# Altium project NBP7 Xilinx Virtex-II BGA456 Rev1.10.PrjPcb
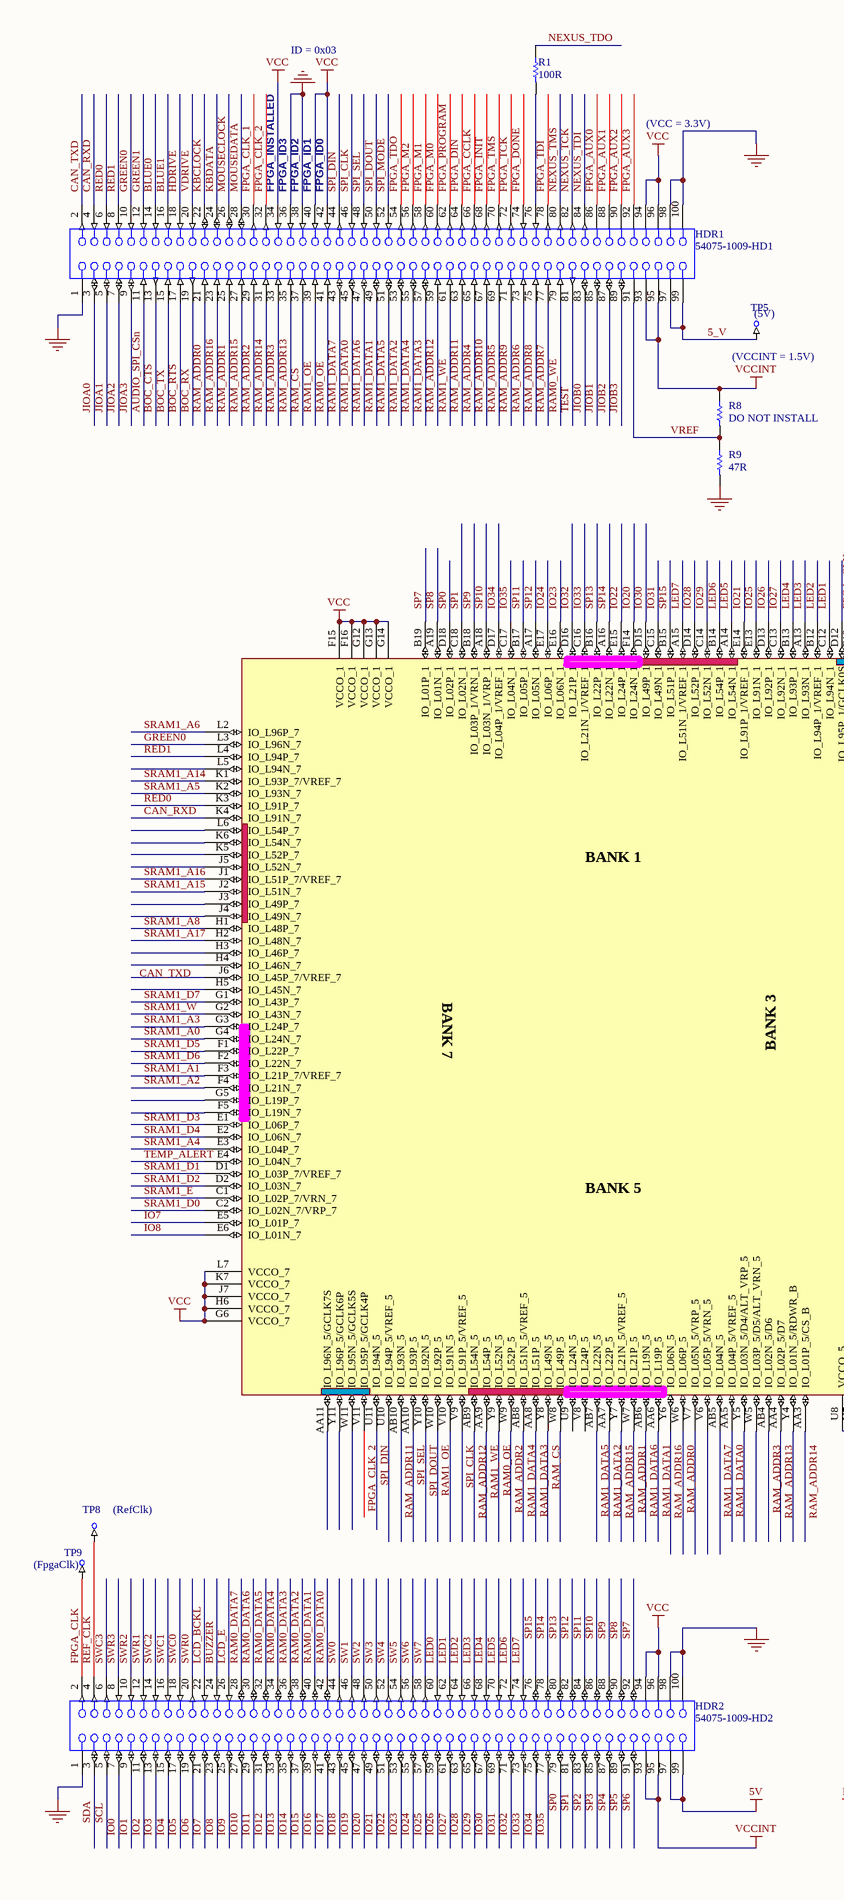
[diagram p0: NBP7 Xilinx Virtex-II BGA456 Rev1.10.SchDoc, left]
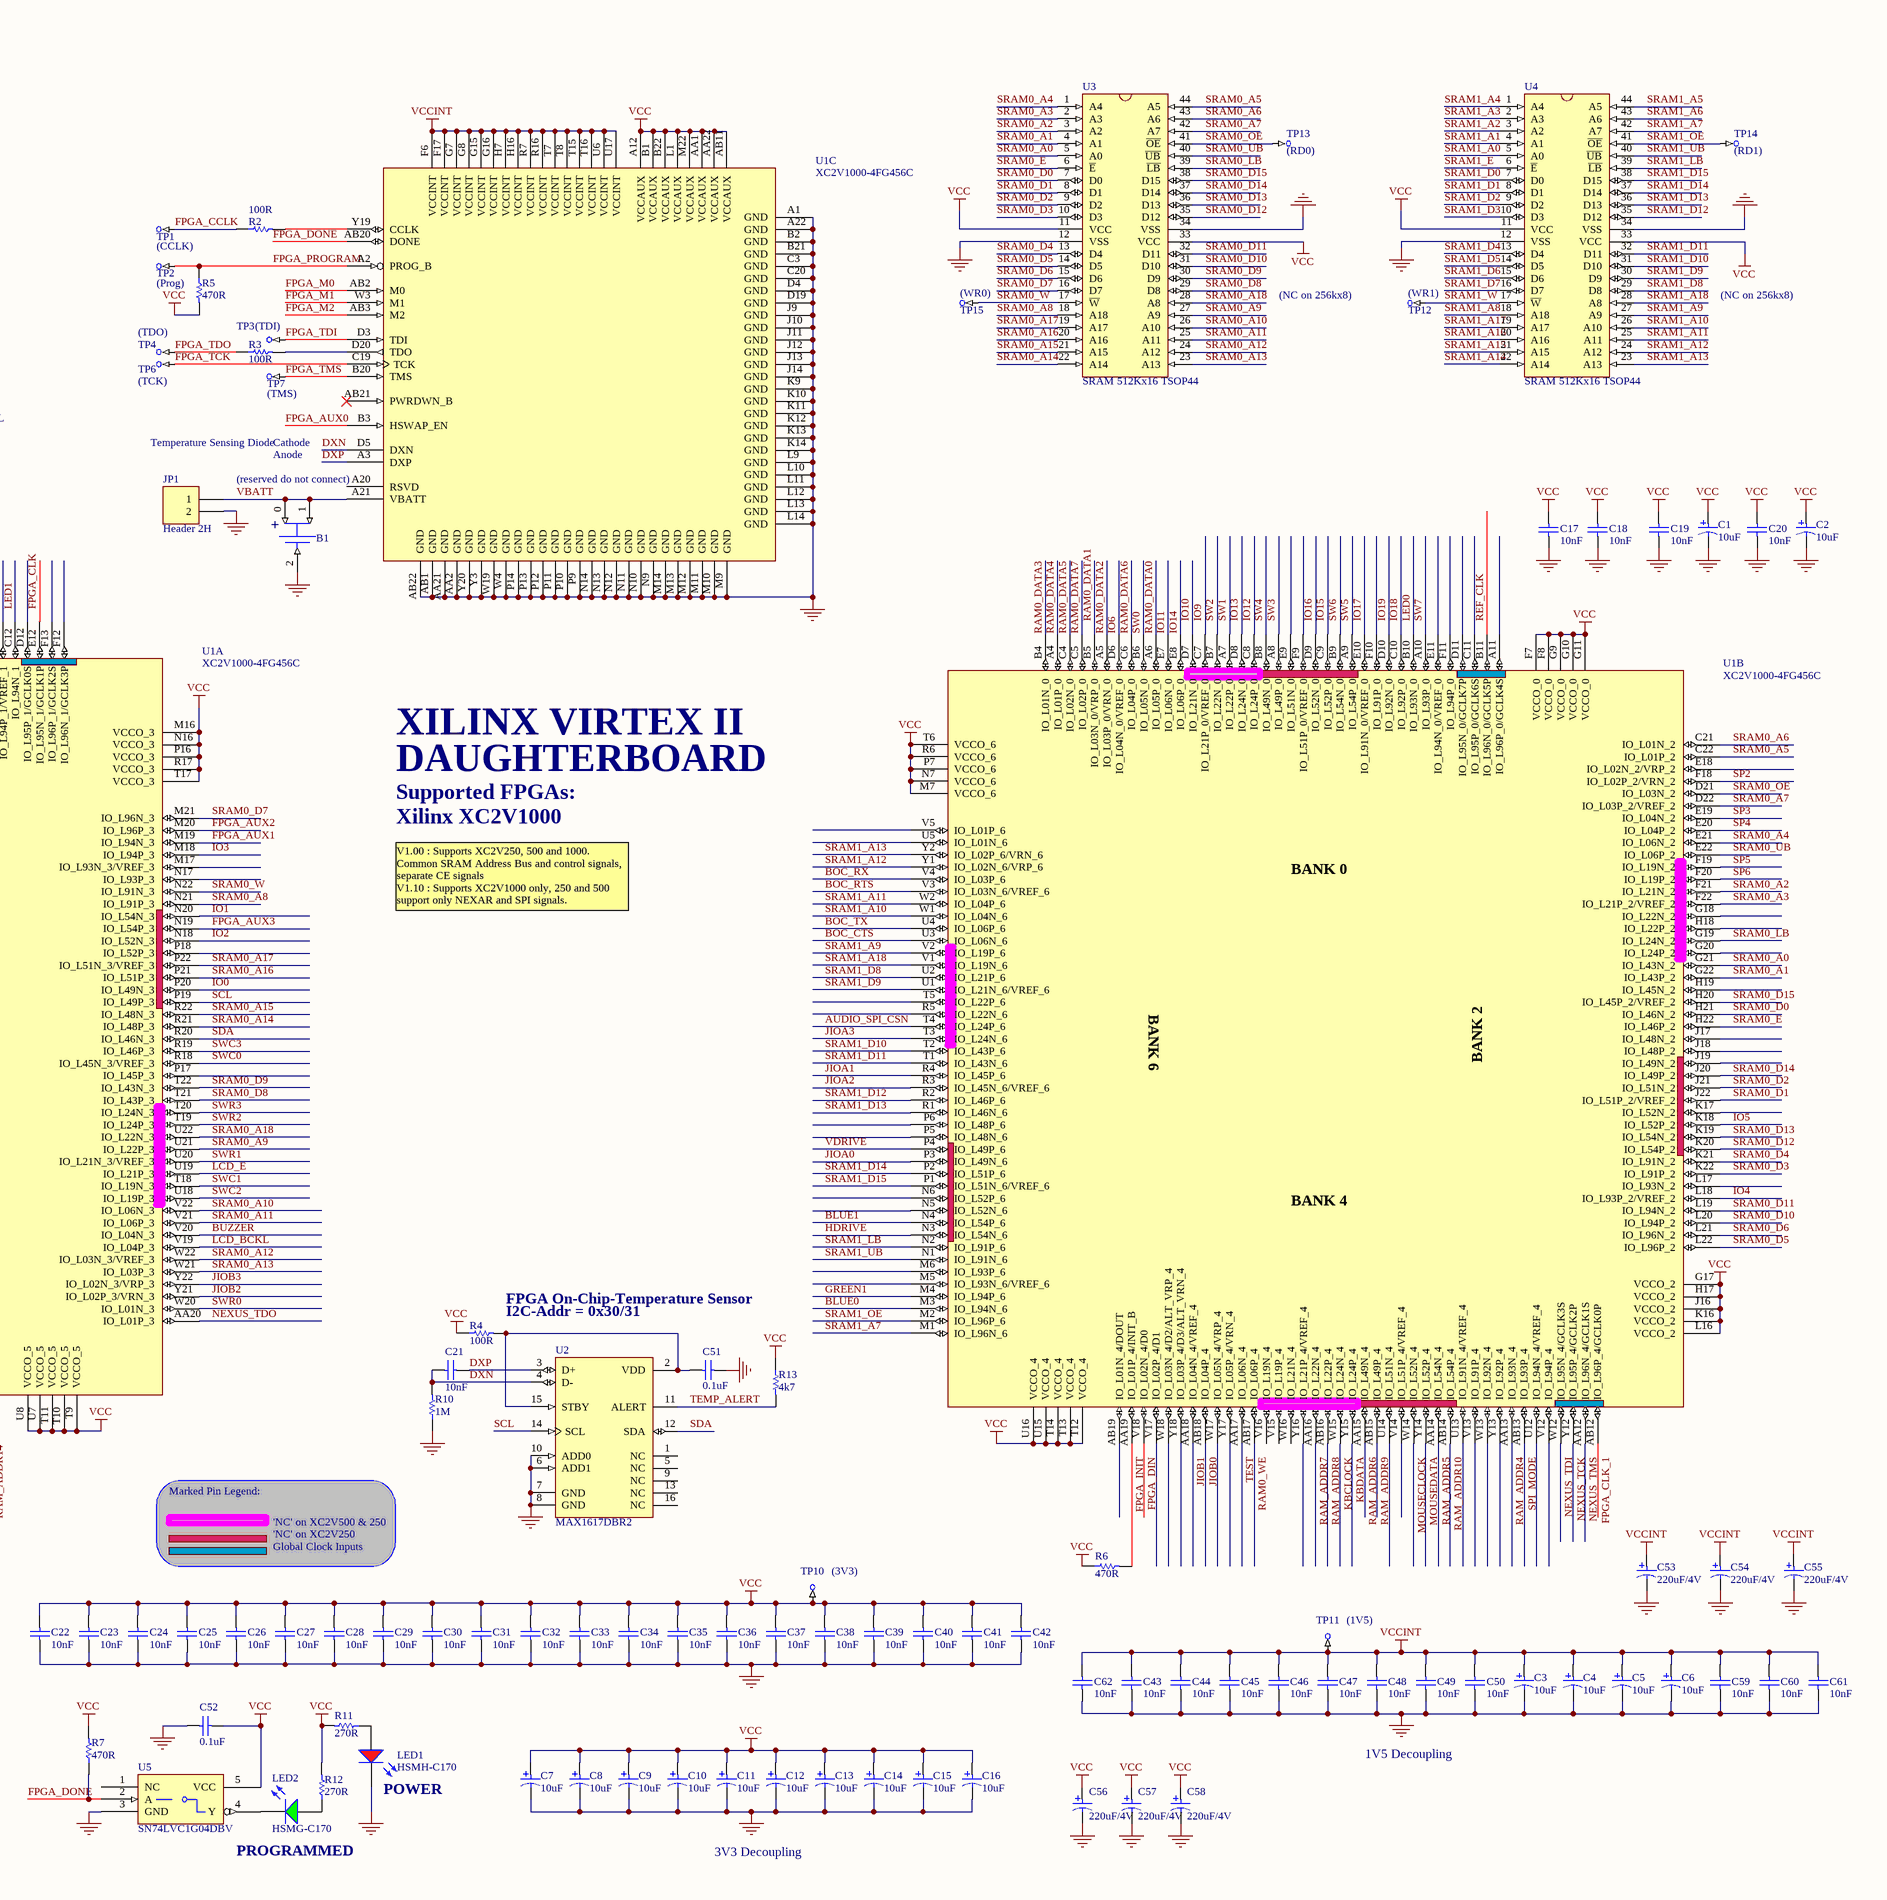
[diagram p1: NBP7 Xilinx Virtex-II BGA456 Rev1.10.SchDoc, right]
1 sheet, 101 parts. Net scope: global (net labels, ports and power ports of the same name join across sheets).
Board file: NBP7 Xilinx Virtex-II BGA456 Rev1.10.PcbDoc

## Sheet NBP7 Xilinx Virtex-II BGA456 Rev1.10.SchDoc: XILINX Virtex II Daughterboard
size A2; DrawnBy: Ch.W.; Organization: Altium Limited; Address1: L3, 12a Rodborough Rd; Address2: Frenchs Forest; Address3: NSW; Address4: Australia 2086; DocumentNumber: 1; Revision: 1.1; SheetNumber: 1; SheetTotal: 1

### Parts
B1  CoinCellHolder  [CoinCellHolder12THM]  (value not drawn)
C1  10uF  [MCCT-B]
C2  10uF  [MCCT-B]
C3  10uF  [MCCT-B]
C4  10uF  [MCCT-B]
C5  10uF  [MCCT-B]
C6  10uF  [MCCT-B]
C7  10uF  [MCCT-B]
C8  10uF  [MCCT-B]
C9  10uF  [MCCT-B]
C10  10uF  [MCCT-B]
C11  10uF  [MCCT-B]
C12  10uF  [MCCT-B]
C13  10uF  [MCCT-B]
C14  10uF  [MCCT-B]
C15  10uF  [MCCT-B]
C16  10uF  [MCCT-B]
C17  10nF  [CC1608-0603]
C18  10nF  [CC1608-0603]
C19  10nF  [CC1608-0603]
C20  10nF  [CC1608-0603]
C21  10nF  [CC1608-0603]
C22  10nF  [CC1608-0603]
C23  10nF  [CC1608-0603]
C24  10nF  [CC1608-0603]
C25  10nF  [CC1608-0603]
C26  10nF  [CC1608-0603]
C27  10nF  [CC1608-0603]
C28  10nF  [CC1608-0603]
C29  10nF  [CC1608-0603]
C30  10nF  [CC1608-0603]
C31  10nF  [CC1608-0603]
C32  10nF  [CC1608-0603]
C33  10nF  [CC1608-0603]
C34  10nF  [CC1608-0603]
C35  10nF  [CC1608-0603]
C36  10nF  [CC1608-0603]
C37  10nF  [CC1608-0603]
C38  10nF  [CC1608-0603]
C39  10nF  [CC1608-0603]
C40  10nF  [CC1608-0603]
C41  10nF  [CC1608-0603]
C42  10nF  [CC1608-0603]
C43  10nF  [CC1608-0603]
C44  10nF  [CC1608-0603]
C45  10nF  [CC1608-0603]
C46  10nF  [CC1608-0603]
C47  10nF  [CC1608-0603]
C48  10nF  [CC1608-0603]
C49  10nF  [CC1608-0603]
C50  10nF  [CC1608-0603]
C51  0.1uF  [CC2012-0805]
C52  0.1uF  [CC2012-0805]
C53  220uF/4V  [MCCT-D]
C54  220uF/4V  [MCCT-D]
C55  220uF/4V  [MCCT-D]
C56  220uF/4V  [MCCT-D]
C57  220uF/4V  [MCCT-D]
C58  220uF/4V  [MCCT-D]
C59  10nF  [CC1608-0603]
C60  10nF  [CC1608-0603]
C61  10nF  [CC1608-0603]
C62  10nF  [CC1608-0603]
HDR1  54075-1009-HD1  [54075]
HDR2  54075-1009-HD2  [54075]
JP1  Header 2H  [HDR1X2H]
LED1  HSMH-C170  [SMD _LED]
LED2  HSMG-C170  [SMD _LED]
R1  100R  [CC2012-0805]
R2  100R  [CC2012-0805]
R3  100R  [CC2012-0805]
R4  100R  [CC2012-0805]
R5  470R  [CC2012-0805]
R6  470R  [CC2012-0805]
R7  470R  [CC2012-0805]
R8  DO NOT INSTALL  [CC2012-0805]
R9  47R  [CC2012-0805]
R10  1M  [CC2012-0805]
R11  270R  [CC2012-0805]
R12  270R  [CC2012-0805]
R13  4k7  [CR2012-0805]
TP1  (CCLK)  [TestPin]  (no BOM)
TP2  (Prog)  [TestPin]  (no BOM)
TP3  (TDI)  [TestPin]  (no BOM)
TP4  (TDO)  [TestPin]  (no BOM)
TP5  (5V)  [TestPin]  (no BOM)
TP6  (TCK)  [TestPin]  (no BOM)
TP7  (TMS)  [TestPin]  (no BOM)
TP8  (RefClk)  [TestPin]  (no BOM)
TP9  (FpgaClk)  [TestPin]  (no BOM)
TP10  (3V3)  [TestPin]  (no BOM)
TP11  (1V5)  [TestPin]  (no BOM)
TP12  (WR1)  [TestPin]  (no BOM)
TP13  (RD0)  [TestPin]  (no BOM)
TP14  (RD1)  [TestPin]  (no BOM)
TP15  (WR0)  [TestPin]  (no BOM)
U1  XC2V1000-4FG456C  [FG456]  (parts A,B,C of 3)
U2  MAX1617DBR2  [QSOP16]
U3  SRAM 512Kx16 TSOP44  [SO-G44/P.8]
U4  SRAM 512Kx16 TSOP44  [SO-G44/P.8]
U5  SN74LVC1G04DBV  [SO-G5/P.95]

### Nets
5V: HDR2.97 HDR2.99
GND: B1.2 C1.2 C2.2 C3.2 C4.2 C5.2 C6.2 C7.2 C8.2 C9.2 C10.2 C11.2 C12.2 C13.2 C14.2 C15.2 C16.2 C17.2 C18.2 C19.2 C20.2 C22.2 C23.2 C24.2 C25.2 C26.2 C27.2 C28.2 C29.2 C30.2 C31.2 C32.2 C33.2 C34.2 C35.2 C36.2 C37.2 C38.2 C39.2 C40.2 C41.2 C42.2 C43.2 C44.2 C45.2 C46.2 C47.2 C48.2 C49.2 C50.2 C51.2 C52.2 C53.2 C54.2 C55.2 C56.2 C57.2 C58.2 C59.2 C60.2 C61.2 C62.2 HDR1.1 HDR1.36 HDR1.38 HDR1.98 HDR1.100 HDR2.1 HDR2.98 HDR2.100 JP1.2 LED1.2(K) R9.2 R10.1 U1.A1(GND) U1.A22(GND) U1.AA2(GND) U1.AA21(GND) U1.AB1(GND) U1.AB22(GND) U1.B2(GND) U1.B21(GND) U1.C3(GND) U1.C20(GND) U1.D4(GND) U1.D19(GND) U1.J9(GND) U1.J10(GND) U1.J11(GND) U1.J12(GND) U1.J13(GND) U1.J14(GND) U1.K9(GND) U1.K10(GND) U1.K11(GND) U1.K12(GND) U1.K13(GND) U1.K14(GND) U1.L9(GND) U1.L10(GND) U1.L11(GND) U1.L12(GND) U1.L13(GND) U1.L14(GND) U1.M9(GND) U1.M10(GND) U1.M11(GND) U1.M12(GND) U1.M13(GND) U1.M14(GND) U1.N9(GND) U1.N10(GND) U1.N11(GND) U1.N12(GND) U1.N13(GND) U1.N14(GND) U1.P9(GND) U1.P10(GND) U1.P11(GND) U1.P12(GND) U1.P13(GND) U1.P14(GND) U1.W4(GND) U1.W19(GND) U1.Y3(GND) U1.Y20(GND) U2.6(ADD1) U2.7(GND) U2.8(GND) U2.10(ADD0) U3.12(VSS) U3.34(VSS) U4.12(VSS) U4.34(VSS) U5.3(GND)
VCC: C1.1 C2.1 C7.1 C8.1 C9.1 C10.1 C11.1 C12.1 C13.1 C14.1 C15.1 C16.1 C17.1 C18.1 C19.1 C20.1 C22.1 C23.1 C24.1 C25.1 C26.1 C27.1 C28.1 C29.1 C30.1 C31.1 C32.1 C33.1 C34.1 C35.1 C36.1 C37.1 C38.1 C39.1 C40.1 C41.1 C42.1 C52.1 C56.1 C57.1 C58.1 HDR1.34 HDR1.40 HDR1.42 HDR1.94 HDR1.96 HDR2.94 HDR2.96 R4.1 R5.2 R6.1 R7.2 R11.2 R12.2 R13.1 TP10.1 U1.A12(VCCAUX) U1.AA1(VCCAUX) U1.AA22(VCCAUX) U1.AB11(VCCAUX) U1.B1(VCCAUX) U1.B22(VCCAUX) U1.F7(VCCO_0) U1.F8(VCCO_0) U1.F15(VCCO_1) U1.F16(VCCO_1) U1.G6(VCCO_7) U1.G9(VCCO_0) U1.G10(VCCO_0) U1.G11(VCCO_0) U1.G12(VCCO_1) U1.G13(VCCO_1) U1.G14(VCCO_1) U1.G17(VCCO_2) U1.H6(VCCO_7) U1.H17(VCCO_2) U1.J7(VCCO_7) U1.J16(VCCO_2) U1.K7(VCCO_7) U1.K16(VCCO_2) U1.L1(VCCAUX) U1.L7(VCCO_7) U1.L16(VCCO_2) U1.M7(VCCO_6) U1.M16(VCCO_3) U1.M22(VCCAUX) U1.N7(VCCO_6) U1.N16(VCCO_3) U1.P7(VCCO_6) U1.P16(VCCO_3) U1.R6(VCCO_6) U1.R17(VCCO_3) U1.T6(VCCO_6) U1.T9(VCCO_5) U1.T10(VCCO_5) U1.T11(VCCO_5) U1.T12(VCCO_4) U1.T13(VCCO_4) U1.T14(VCCO_4) U1.T17(VCCO_3) U1.U7(VCCO_5) U1.U8(VCCO_5) U1.U15(VCCO_4) U1.U16(VCCO_4) U3.11(VCC) U3.33(VCC) U4.11(VCC) U4.33(VCC) U5.5(VCC)
VCCINT: C3.1 C4.1 C5.1 C6.1 C43.1 C44.1 C45.1 C46.1 C47.1 C48.1 C49.1 C50.1 C53.1 C54.1 C55.1 C59.1 C60.1 C61.1 C62.1 HDR1.93 HDR1.95 HDR2.93 HDR2.95 R8.1 TP11.1 U1.F6(VCCINT) U1.F17(VCCINT) U1.G7(VCCINT) U1.G8(VCCINT) U1.G15(VCCINT) U1.G16(VCCINT) U1.H7(VCCINT) U1.H16(VCCINT) U1.R7(VCCINT) U1.R16(VCCINT) U1.T7(VCCINT) U1.T8(VCCINT) U1.T15(VCCINT) U1.T16(VCCINT) U1.U6(VCCINT) U1.U17(VCCINT)
5_V: HDR1.97 HDR1.99 TP5.1
AUDIO_SPI_CSn: HDR1.11 U1.T4(IO_L24P_6)
BLUE0: HDR1.14 U1.M3(IO_L94N_6)
BLUE1: HDR1.16 U1.N4(IO_L54P_6)
BOC_CTS: HDR1.13 U1.U3(IO_L06N_6)
BOC_RTS: HDR1.17 U1.V3(IO_L03N_6/VREF_6)
BOC_RX: HDR1.19 U1.V4(IO_L03P_6)
BOC_TX: HDR1.15 U1.U4(IO_L06P_6)
BUZZER: HDR2.24 U1.V20(IO_L04N_3)
CAN_RXD: HDR1.4 U1.K4(IO_L91N_7)
CAN_TXD: HDR1.2 U1.H4(IO_L46N_7)
DXN: C21.1 R10.2 U1.D5(DXN) U2.4(D-)
DXP: C21.2 U1.A3(DXP) U2.3(D+)
FPGA_AUX0: HDR1.86 U1.B3(HSWAP_EN)
FPGA_AUX1: HDR1.88 U1.M19(IO_L94N_3)
FPGA_AUX2: HDR1.90 U1.M20(IO_L96P_3)
FPGA_AUX3: HDR1.92 U1.N19(IO_L54P_3)
FPGA_CCLK: HDR1.66 R2.1 TP1.1
FPGA_CLK: HDR2.2 TP9.1 U1.E12(IO_L95N_1/GCLK1P)
FPGA_CLK_1: HDR1.30 U1.AB12(IO_L96P_4/GCLK0P)
FPGA_CLK_2: HDR1.32 U1.V11(IO_L95P_5/GCLK4P)
FPGA_DIN: HDR1.64 U1.V18(IO_L02N_4/D0)
FPGA_DONE: HDR1.74 R7.1 U1.AB20(DONE) U5.2(A)
FPGA_INIT: HDR1.68 R6.2 U1.AA19(IO_L01P_4/INIT_B)
FPGA_M0: HDR1.60 U1.AB2(M0)
FPGA_M1: HDR1.58 U1.W3(M1)
FPGA_M2: HDR1.56 U1.AB3(M2)
FPGA_PROGRAM: HDR1.62 R5.1 TP2.1 U1.A2(PROG_B)
FPGA_TCK: HDR1.72 TP6.1 U1.C19(TCK)
FPGA_TDI: HDR1.78 TP3.1 U1.D3(TDI)
FPGA_TDO: HDR1.54 R3.1 TP4.1
FPGA_TMS: HDR1.70 TP7.1 U1.B20(TMS)
GREEN0: HDR1.10 U1.L3(IO_L96N_7)
GREEN1: HDR1.12 U1.M4(IO_L94P_6)
HDRIVE: HDR1.18 U1.N3(IO_L54N_6)
IO0: HDR2.7 U1.P20(IO_L49N_3)
IO1: HDR2.9 U1.N20(IO_L54N_3)
IO2: HDR2.11 U1.N18(IO_L52N_3)
IO3: HDR2.13 U1.M18(IO_L94P_3)
IO4: HDR2.15 U1.L18(IO_L93P_2/VREF_2)
IO5: HDR2.17 U1.K18(IO_L52P_2)
IO6: HDR2.19 U1.D6(IO_L04N_0/VREF_0)
IO7: HDR2.21 U1.E5(IO_L01P_7)
IO8: HDR2.23 U1.E6(IO_L01N_7)
IO9: HDR2.25 U1.C7(IO_L21P_0/VREF_0)
IO10: HDR2.27 U1.D7(IO_L21N_0)
IO11: HDR2.29 U1.E7(IO_L06N_0)
IO12: HDR2.31 U1.C8(IO_L24P_0)
IO13: HDR2.33 U1.D8(IO_L24N_0)
IO14: HDR2.35 U1.E8(IO_L06P_0)
IO15: HDR2.37 U1.C9(IO_L52P_0)
IO16: HDR2.39 U1.D9(IO_L52N_0)
IO17: HDR2.41 U1.E10(IO_L91N_0/VREF_0)
IO18: HDR2.43 U1.C10(IO_L92P_0)
IO19: HDR2.45 U1.D10(IO_L92N_0)
IO20: HDR2.47 U1.F14(IO_L24N_1)
IO21: HDR2.49 U1.E14(IO_L91P_1/VREF_1)
IO22: HDR2.51 U1.E15(IO_L24P_1)
IO23: HDR2.53 U1.E16(IO_L06N_1)
IO24: HDR2.55 U1.E17(IO_L06P_1)
IO25: HDR2.57 U1.E13(IO_L91N_1)
IO26: HDR2.59 U1.D13(IO_L92P_1)
IO27: HDR2.61 U1.C13(IO_L92N_1)
IO28: HDR2.63 U1.D14(IO_L52P_1)
IO29: HDR2.65 U1.C14(IO_L52N_1)
IO30: HDR2.67 U1.D15(IO_L49P_1)
IO31: HDR2.69 U1.C15(IO_L49N_1)
IO32: HDR2.71 U1.D16(IO_L21P_1)
IO33: HDR2.73 U1.C16(IO_L21N_1/VREF_1)
IO34: HDR2.75 U1.D17(IO_L04P_1/VREF_1)
IO35: HDR2.77 U1.C17(IO_L04N_1)
JIOA0: HDR1.3 U1.P3(IO_L49N_6)
JIOA1: HDR1.5 U1.R4(IO_L45P_6)
JIOA2: HDR1.7 U1.R3(IO_L45N_6/VREF_6)
JIOA3: HDR1.9 U1.T3(IO_L24N_6)
JIOB0: HDR1.83 U1.AB18(IO_L04P_4)
JIOB1: HDR1.85 U1.AA18(IO_L04N_4/VREF_4)
JIOB2: HDR1.87 U1.Y21(IO_L02P_3/VRN_3)
JIOB3: HDR1.89 U1.Y22(IO_L02N_3/VRP_3)
KBCLOCK: HDR1.22 U1.W15(IO_L24N_4)
KBDATA: HDR1.24 U1.Y15(IO_L24P_4)
LCD_BCKL: HDR2.22 U1.V19(IO_L04P_3)
LCD_E: HDR2.26 U1.U19(IO_L21P_3)
LED0: HDR2.60 U1.B10(IO_L93N_0)
LED1: HDR2.62 U1.C12(IO_L94N_1)
LED2: HDR2.64 U1.B12(IO_L94P_1/VREF_1)
LED3: HDR2.66 U1.A13(IO_L93N_1)
LED4: HDR2.68 U1.B13(IO_L93P_1)
LED5: HDR2.70 U1.A14(IO_L54N_1)
LED6: HDR2.72 U1.B14(IO_L54P_1)
LED7: HDR2.74 U1.A15(IO_L51N_1/VREF_1)
MOUSECLOCK: HDR1.26 U1.W14(IO_L52N_4)
MOUSEDATA: HDR1.28 U1.Y14(IO_L52P_4)
NEXUS_TCK: HDR1.82 U1.Y12(IO_L95P_4/GCLK2P)
NEXUS_TDI: HDR1.84 U1.W12(IO_L95N_4/GCLK3S)
NEXUS_TDO: R1.1 U1.AA20(IO_L01P_3)
NEXUS_TMS: HDR1.80 U1.AA12(IO_L96N_4/GCLK1S)
RAM0_DATA0: HDR2.42 U1.A6(IO_L05P_0)
RAM0_DATA1: HDR2.40 U1.B5(IO_L03N_0/VRP_0)
RAM0_DATA2: HDR2.38 U1.A5(IO_L03P_0/VRN_0)
RAM0_DATA3: HDR2.36 U1.B4(IO_L01N_0)
RAM0_DATA4: HDR2.34 U1.A4(IO_L01P_0)
RAM0_DATA5: HDR2.32 U1.C4(IO_L02N_0)
RAM0_DATA6: HDR2.30 U1.C6(IO_L04P_0)
RAM0_DATA7: HDR2.28 U1.C5(IO_L02P_0)
RAM0_OE: HDR1.41 U1.Y9(IO_L52N_5)
RAM0_WE: HDR1.79 U1.AB17(IO_L06P_4)
RAM1_DATA0: HDR1.45 U1.AA5(IO_L04P_5/VREF_5)
RAM1_DATA1: HDR1.49 U1.AA6(IO_L19P_5)
RAM1_DATA2: HDR1.53 U1.AA7(IO_L22P_5)
RAM1_DATA3: HDR1.57 U1.AA8(IO_L51P_5)
RAM1_DATA4: HDR1.55 U1.AB8(IO_L51N_5/VREF_5)
RAM1_DATA5: HDR1.51 U1.AB7(IO_L22N_5)
RAM1_DATA6: HDR1.47 U1.AB6(IO_L19N_5)
RAM1_DATA7: HDR1.43 U1.AB5(IO_L04N_5)
RAM1_OE: HDR1.39 U1.W10(IO_L92P_5)
RAM1_WE: HDR1.61 U1.AA9(IO_L54P_5)
RAM_ADDR0: HDR1.21 U1.W6(IO_L06P_5)
RAM_ADDR1: HDR1.25 U1.W7(IO_L21P_5)
RAM_ADDR2: HDR1.29 U1.W9(IO_L52P_5)
RAM_ADDR3: HDR1.33 U1.AB4(IO_L02N_5/D6)
RAM_ADDR4: HDR1.65 U1.AA13(IO_L93N_4)
RAM_ADDR5: HDR1.69 U1.AA14(IO_L54N_4)
RAM_ADDR6: HDR1.73 U1.AA15(IO_L49N_4)
RAM_ADDR7: HDR1.77 U1.AA16(IO_L22N_4)
RAM_ADDR8: HDR1.75 U1.AB16(IO_L22P_4)
RAM_ADDR9: HDR1.71 U1.AB15(IO_L49P_4)
RAM_ADDR10: HDR1.67 U1.AB14(IO_L54P_4)
RAM_ADDR11: HDR1.63 U1.AB10(IO_L93N_5)
RAM_ADDR12: HDR1.59 U1.AB9(IO_L54N_5)
RAM_ADDR13: HDR1.35 U1.AA4(IO_L02P_5/D7)
RAM_ADDR14: HDR1.31 U1.AA3(IO_L01P_5/CS_B)
RAM_ADDR15: HDR1.27 U1.Y7(IO_L21N_5/VREF_5)
RAM_ADDR16: HDR1.23 U1.Y6(IO_L06N_5)
RAM_CS: HDR1.37 U1.Y8(IO_L49N_5)
RED0: HDR1.6 U1.K3(IO_L91P_7)
RED1: HDR1.8 U1.L4(IO_L94P_7)
REF_CLK: HDR2.4 TP8.1 U1.B11(IO_L96N_0/GCLK5P)
SCL: HDR2.5 U1.P19(IO_L49P_3) U2.14(SCL)
SDA: HDR2.3 U1.R20(IO_L46N_3) U2.12(SDA)
SP0: HDR2.79 U1.D18(IO_L02P_1)
SP1: HDR2.81 U1.C18(IO_L02N_1)
SP2: HDR2.83 U1.F18(IO_L02P_2/VRN_2)
SP3: HDR2.85 U1.E19(IO_L04N_2)
SP4: HDR2.87 U1.E20(IO_L04P_2)
SP5: HDR2.89 U1.F19(IO_L19N_2)
SP6: HDR2.91 U1.F20(IO_L19P_2)
SP7: HDR2.92 U1.B19(IO_L01P_1)
SP8: HDR2.90 U1.A19(IO_L01N_1)
SP9: HDR2.88 U1.B18(IO_L03P_1/VRN_1)
SP10: HDR2.86 U1.A18(IO_L03N_1/VRP_1)
SP11: HDR2.84 U1.B17(IO_L05P_1)
SP12: HDR2.82 U1.A17(IO_L05N_1)
SP13: HDR2.80 U1.B16(IO_L22P_1)
SP14: HDR2.78 U1.A16(IO_L22N_1)
SP15: HDR2.76 U1.B15(IO_L51P_1)
SPI_CLK: HDR1.46 U1.V9(IO_L91P_5/VREF_5)
SPI_DIN: HDR1.44 U1.U11(IO_L94N_5)
SPI_DOUT: HDR1.50 U1.Y10(IO_L92N_5)
SPI_MODE: HDR1.52 U1.AB13(IO_L93P_4)
SPI_SEL: HDR1.48 U1.AA10(IO_L93P_5)
SRAM0_A0: U1.G21(IO_L43N_2) U3.5(A0)
SRAM0_A1: U1.G22(IO_L43P_2) U3.4(A1)
SRAM0_A2: U1.F21(IO_L21N_2) U3.3(A2)
SRAM0_A3: U1.F22(IO_L21P_2/VREF_2) U3.2(A3)
SRAM0_A4: U1.E21(IO_L06N_2) U3.1(A4)
SRAM0_A5: U1.C22(IO_L01P_2) U3.44(A5)
SRAM0_A6: U1.C21(IO_L01N_2) U3.43(A6)
SRAM0_A7: U1.D22(IO_L03P_2/VREF_2) U3.42(A7)
SRAM0_A8: U1.N21(IO_L91P_3) U3.18(A18)
SRAM0_A9: U1.U21(IO_L22P_3) U3.27(A9)
SRAM0_A10: U1.V22(IO_L06N_3) U3.26(A10)
SRAM0_A11: U1.V21(IO_L06P_3) U3.25(A11)
SRAM0_A12: U1.W22(IO_L03N_3/VREF_3) U3.24(A12)
SRAM0_A13: U1.W21(IO_L03P_3) U3.23(A13)
SRAM0_A14: U1.R21(IO_L48P_3) U3.22(A14)
SRAM0_A15: U1.R22(IO_L48N_3) U3.21(A15)
SRAM0_A16: U1.P21(IO_L51P_3) U3.20(A16)
SRAM0_A17: U1.P22(IO_L51N_3/VREF_3) U3.19(A17)
SRAM0_A18: U1.U22(IO_L22N_3) U3.28(A8)
SRAM0_D0: U1.H21(IO_L46N_2) U3.7(D0)
SRAM0_D1: U1.J22(IO_L51P_2/VREF_2) U3.8(D1)
SRAM0_D2: U1.J21(IO_L51N_2) U3.9(D2)
SRAM0_D3: U1.K22(IO_L91P_2) U3.10(D3)
SRAM0_D4: U1.K21(IO_L91N_2) U3.13(D4)
SRAM0_D5: U1.L22(IO_L96P_2) U3.14(D5)
SRAM0_D6: U1.L21(IO_L96N_2) U3.15(D6)
SRAM0_D7: U1.M21(IO_L96N_3) U3.16(D7)
SRAM0_D8: U1.T21(IO_L43P_3) U3.29(D8)
SRAM0_D9: U1.T22(IO_L43N_3) U3.30(D9)
SRAM0_D10: U1.L20(IO_L94P_2) U3.31(D10)
SRAM0_D11: U1.L19(IO_L94N_2) U3.32(D11)
SRAM0_D12: U1.K20(IO_L54P_2) U3.35(D12)
SRAM0_D13: U1.K19(IO_L54N_2) U3.36(D13)
SRAM0_D14: U1.J20(IO_L49P_2) U3.37(D14)
SRAM0_D15: U1.H20(IO_L45P_2/VREF_2) U3.38(D15)
SRAM0_E: U1.H22(IO_L46P_2) U3.6(~{E})
SRAM0_LB: U1.G19(IO_L24N_2) U3.39(~{LB})
SRAM0_OE: TP13.1 U1.D21(IO_L03N_2) U3.41(~{OE})
SRAM0_UB: U1.E22(IO_L06P_2) U3.40(~{UB})
SRAM0_W: TP15.1 U1.N22(IO_L91N_3) U3.17(~{W})
SRAM1_A0: U1.G4(IO_L24N_7) U4.5(A0)
SRAM1_A1: U1.F3(IO_L21P_7/VREF_7) U4.4(A1)
SRAM1_A2: U1.F4(IO_L21N_7) U4.3(A2)
SRAM1_A3: U1.G3(IO_L24P_7) U4.2(A3)
SRAM1_A4: U1.E3(IO_L04P_7) U4.1(A4)
SRAM1_A5: U1.K2(IO_L93N_7) U4.44(A5)
SRAM1_A6: U1.L2(IO_L96P_7) U4.43(A6)
SRAM1_A7: U1.M1(IO_L96N_6) U4.42(A7)
SRAM1_A8: U1.H1(IO_L48P_7) U4.18(A18)
SRAM1_A9: U1.V2(IO_L19P_6) U4.27(A9)
SRAM1_A10: U1.W1(IO_L04N_6) U4.26(A10)
SRAM1_A11: U1.W2(IO_L04P_6) U4.25(A11)
SRAM1_A12: U1.Y1(IO_L02N_6/VRP_6) U4.24(A12)
SRAM1_A13: U1.Y2(IO_L02P_6/VRN_6) U4.23(A13)
SRAM1_A14: U1.K1(IO_L93P_7/VREF_7) U4.22(A14)
SRAM1_A15: U1.J2(IO_L51N_7) U4.21(A15)
SRAM1_A16: U1.J1(IO_L51P_7/VREF_7) U4.20(A16)
SRAM1_A17: U1.H2(IO_L48N_7) U4.19(A17)
SRAM1_A18: U1.V1(IO_L19N_6) U4.28(A8)
SRAM1_D0: U1.C2(IO_L02N_7/VRP_7) U4.7(D0)
SRAM1_D1: U1.D1(IO_L03P_7/VREF_7) U4.8(D1)
SRAM1_D2: U1.D2(IO_L03N_7) U4.9(D2)
SRAM1_D3: U1.E1(IO_L06P_7) U4.10(D3)
SRAM1_D4: U1.E2(IO_L06N_7) U4.13(D4)
SRAM1_D5: U1.F1(IO_L22P_7) U4.14(D5)
SRAM1_D6: U1.F2(IO_L22N_7) U4.15(D6)
SRAM1_D7: U1.G1(IO_L43P_7) U4.16(D7)
SRAM1_D8: U1.U2(IO_L21P_6) U4.29(D8)
SRAM1_D9: U1.U1(IO_L21N_6/VREF_6) U4.30(D9)
SRAM1_D10: U1.T2(IO_L43P_6) U4.31(D10)
SRAM1_D11: U1.T1(IO_L43N_6) U4.32(D11)
SRAM1_D12: U1.R2(IO_L46P_6) U4.35(D12)
SRAM1_D13: U1.R1(IO_L46N_6) U4.36(D13)
SRAM1_D14: U1.P2(IO_L51P_6) U4.37(D14)
SRAM1_D15: U1.P1(IO_L51N_6/VREF_6) U4.38(D15)
SRAM1_E: U1.C1(IO_L02P_7/VRN_7) U4.6(~{E})
SRAM1_LB: U1.N2(IO_L91P_6) U4.39(~{LB})
SRAM1_OE: TP14.1 U1.M2(IO_L96P_6) U4.41(~{OE})
SRAM1_UB: U1.N1(IO_L91N_6) U4.40(~{UB})
SRAM1_W: TP12.1 U1.G2(IO_L43N_7) U4.17(~{W})
SW0: HDR2.44 U1.B6(IO_L05N_0)
SW1: HDR2.46 U1.A7(IO_L22P_0)
SW2: HDR2.48 U1.B7(IO_L22N_0)
SW3: HDR2.50 U1.A8(IO_L49P_0)
SW4: HDR2.52 U1.B8(IO_L49N_0)
SW5: HDR2.54 U1.A9(IO_L54P_0)
SW6: HDR2.56 U1.B9(IO_L54N_0)
SW7: HDR2.58 U1.A10(IO_L93P_0)
SWC0: HDR2.18 U1.R18(IO_L45N_3/VREF_3)
SWC1: HDR2.16 U1.T18(IO_L19N_3)
SWC2: HDR2.14 U1.U18(IO_L19P_3)
SWC3: HDR2.6 U1.R19(IO_L46P_3)
SWR0: HDR2.20 U1.W20(IO_L01N_3)
SWR1: HDR2.12 U1.U20(IO_L21N_3/VREF_3)
SWR2: HDR2.10 U1.T19(IO_L24P_3)
SWR3: HDR2.8 U1.T20(IO_L24N_3)
TEMP_ALERT: R13.2 U1.E4(IO_L04N_7) U2.11(ALERT)
TEST: HDR1.81 U1.AA17(IO_L06N_4)
VBATT: B1.0 B1.1 JP1.1 U1.A21(VBATT)
VDRIVE: HDR1.20 U1.P4(IO_L49P_6)
VREF: HDR1.91 R8.2 R9.1
NetC51_1: C51.1 R4.2 U2.2(VDD) U2.15(STBY)
NetHDR1_76: HDR1.76 R1.2
NetLED1_1: LED1.1(A) R11.1
NetLED2_1: LED2.1(A) R12.1
NetLED2_2: LED2.2(K) U5.4(Y)
NetR2_2: R2.2 U1.Y19(CCLK)
NetR3_2: R3.2 U1.D20(TDO)

Not connected (* = marked no-connect by the designer): U1 A11(IO_L96P_0/GCLK4S) A20(RSVD) AA11(IO_L96N_5/GCLK7S) AB19(IO_L01N_4/DOUT) AB21(PWRDWN_B)* C11(IO_L95P_0/GCLK6S) D11(IO_L95N_0/GCLK7P) D12(IO_L95P_1/GCLK0S) E9(IO_L51N_0) E11(IO_L94N_0/VREF_0) E18(IO_L02N_2/VRP_2) F5(IO_L19N_7) F9(IO_L51P_0/VREF_0) F10(IO_L91P_0) F11(IO_L94P_0) F12(IO_L96N_1/GCLK3P) F13(IO_L96P_1/GCLK2S) G5(IO_L19P_7) G18(IO_L22N_2) G20(IO_L24P_2) H3(IO_L46P_7) H5(IO_L45N_7) H18(IO_L22P_2) H19(IO_L45N_2) J3(IO_L49P_7) J4(IO_L49N_7) J5(IO_L52N_7) J6(IO_L45P_7/VREF_7) J17(IO_L48N_2) J18(IO_L48P_2) J19(IO_L49N_2) K5(IO_L52P_7) K6(IO_L54N_7) K17(IO_L52N_2) L5(IO_L94N_7) L6(IO_L54P_7) L17(IO_L93N_2) M5(IO_L93N_6/VREF_6) M6(IO_L93P_6) M17(IO_L93N_3/VREF_3) N5(IO_L52N_6) N6(IO_L52P_6) N17(IO_L93P_3) P5(IO_L48N_6) P6(IO_L48P_6) P17(IO_L45P_3) P18(IO_L52P_3) R5(IO_L22N_6) T5(IO_L22P_6) U5(IO_L01N_6) U9(IO_L24N_5) U10(IO_L94P_5/VREF_5) U12(IO_L94N_4/VREF_4) U13(IO_L91N_4/VREF_4) U14(IO_L51N_4) V5(IO_L01P_6) V6(IO_L05P_5/VRN_5) V7(IO_L05N_5/VRP_5) V8(IO_L24P_5) V10(IO_L91N_5) V12(IO_L94P_4) V13(IO_L91P_4) V14(IO_L51P_4/VREF_4) V15(IO_L19P_4) V16(IO_L19N_4) V17(IO_L02P_4/D1) W5(IO_L03P_5/D5/ALT_VRN_5) W8(IO_L49P_5) W11(IO_L95N_5/GCLK5S) W13(IO_L92N_4) W16(IO_L21N_4) W17(IO_L05N_4/VRP_4) W18(IO_L03N_4/D2/ALT_VRP_4) Y4(IO_L01N_5/RDWR_B) Y5(IO_L03N_5/D4/ALT_VRP_5) Y11(IO_L96P_5/GCLK6P) Y13(IO_L92P_4) Y16(IO_L21P_4/VREF_4) Y17(IO_L05P_4/VRN_4) Y18(IO_L03P_4/D3/ALT_VRN_4); U2 1(NC) 5(NC) 9(NC) 13(NC) 16(NC); U5 1(NC)

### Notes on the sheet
- ID = 0x03
- (VCC = 3.3V)
- (near HDR1) FPGA_INSTALLED
- (near HDR1) FPGA_ID3
- (near HDR1) FPGA_ID2
- (near HDR1) FPGA_ID1
- (near HDR1) FPGA_ID0
- (NC on 256kx8)
- (VCCINT = 1.5V)
- Temperature Sensing Diode
- Anode
- Cathode
- (near U1) (reserved do not connect)
- XILINX VIRTEX II
- DAUGHTERBOARD
- Supported FPGAs:
- Xilinx XC2V1000
- V1.00 : Supports XC2V250, 500 and 1000. Common SRAM Address Bus and control signals, separate CE signals
  V1.10 : Supports XC2V1000 only, 250 and 500 support only NEXAR and SPI signals.
- (near R4) FPGA On-Chip-Temperature Sensor
- (near R4) I2C-Addr = 0x30/31
- Marked Pin Legend:
- 'NC' on XC2V250
- Global Clock Inputs
- 'NC' on XC2V500 & 250
- (near LED1) POWER
- 1V5 Decoupling
- PROGRAMMED
- 3V3 Decoupling

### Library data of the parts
C1-C16 C53-C58 = CAP_POLAR: Polar Capacitor
C17-C52 C59-C62 = CAP: Capacitor
HDR1 = 54075-1009-HD1: Board-to-Board, Docking Station, 0.80mm (.031") Pitch, Shielded Receptacle, Vertical, Ultra Low Profile, SMT; Manufacturer: Molex; Package Information: Latest Revision: Jun-2001; Mating Height: 8.5mm; Voltage: 100V; Current: 0.5A; Contact Resistance: 40mOhm max; PCB Layout: Complies with Manufacturer's Recommendation.
HDR2 = 54075-1009-HD2: Board-to-Board, Docking Station, 0.80mm (.031") Pitch, Shielded Receptacle, Vertical, Ultra Low Profile, SMT; Manufacturer: Molex; Package Information: Latest Revision: Jun-2001; Mating Height: 8.5mm; Voltage: 100V; Current: 0.5A; Contact Resistance: 40mOhm max; PCB Layout: Complies with Manufacturer's Recommendation.
JP1 = Header 2H: Header, 2-Pin, Right Angle
LED1 = HSMX-C670: Typical RED GaAs SMD LED Agilent make; Manufacturer: Generic Components; Class I: Optoelectronic; Fitted: True
LED2 = HSMX-C670: Typical GREEN GaAs SMD LED Agilent make; Manufacturer: Generic Components; Class I: Optoelectronic; Fitted: True
R1-R13 = RES: Resistor
TP1-TP15 = TestPin
U1 = XC2V1000-4FG456C: Virtex-II 1.5V FPGA, 456-Ball FBGA, Commercial Grade; Package Information: Latest Revision: ver1.1, Apr-2001; Code - JEDEC: MO-151-AAJ-1
U2 = MAX1617DBR2: SMBus Temperature Sensor with Internal and External Diode Input; Package Information: Latest Revision: Feb-2000
U3 U4 = SRAM 512Kx16 TSOP44: 512Kx16Bit SRAM TSOP44
U5 = SN74AHC1G04DBVR: Manufacturer: TI; Fitted: True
